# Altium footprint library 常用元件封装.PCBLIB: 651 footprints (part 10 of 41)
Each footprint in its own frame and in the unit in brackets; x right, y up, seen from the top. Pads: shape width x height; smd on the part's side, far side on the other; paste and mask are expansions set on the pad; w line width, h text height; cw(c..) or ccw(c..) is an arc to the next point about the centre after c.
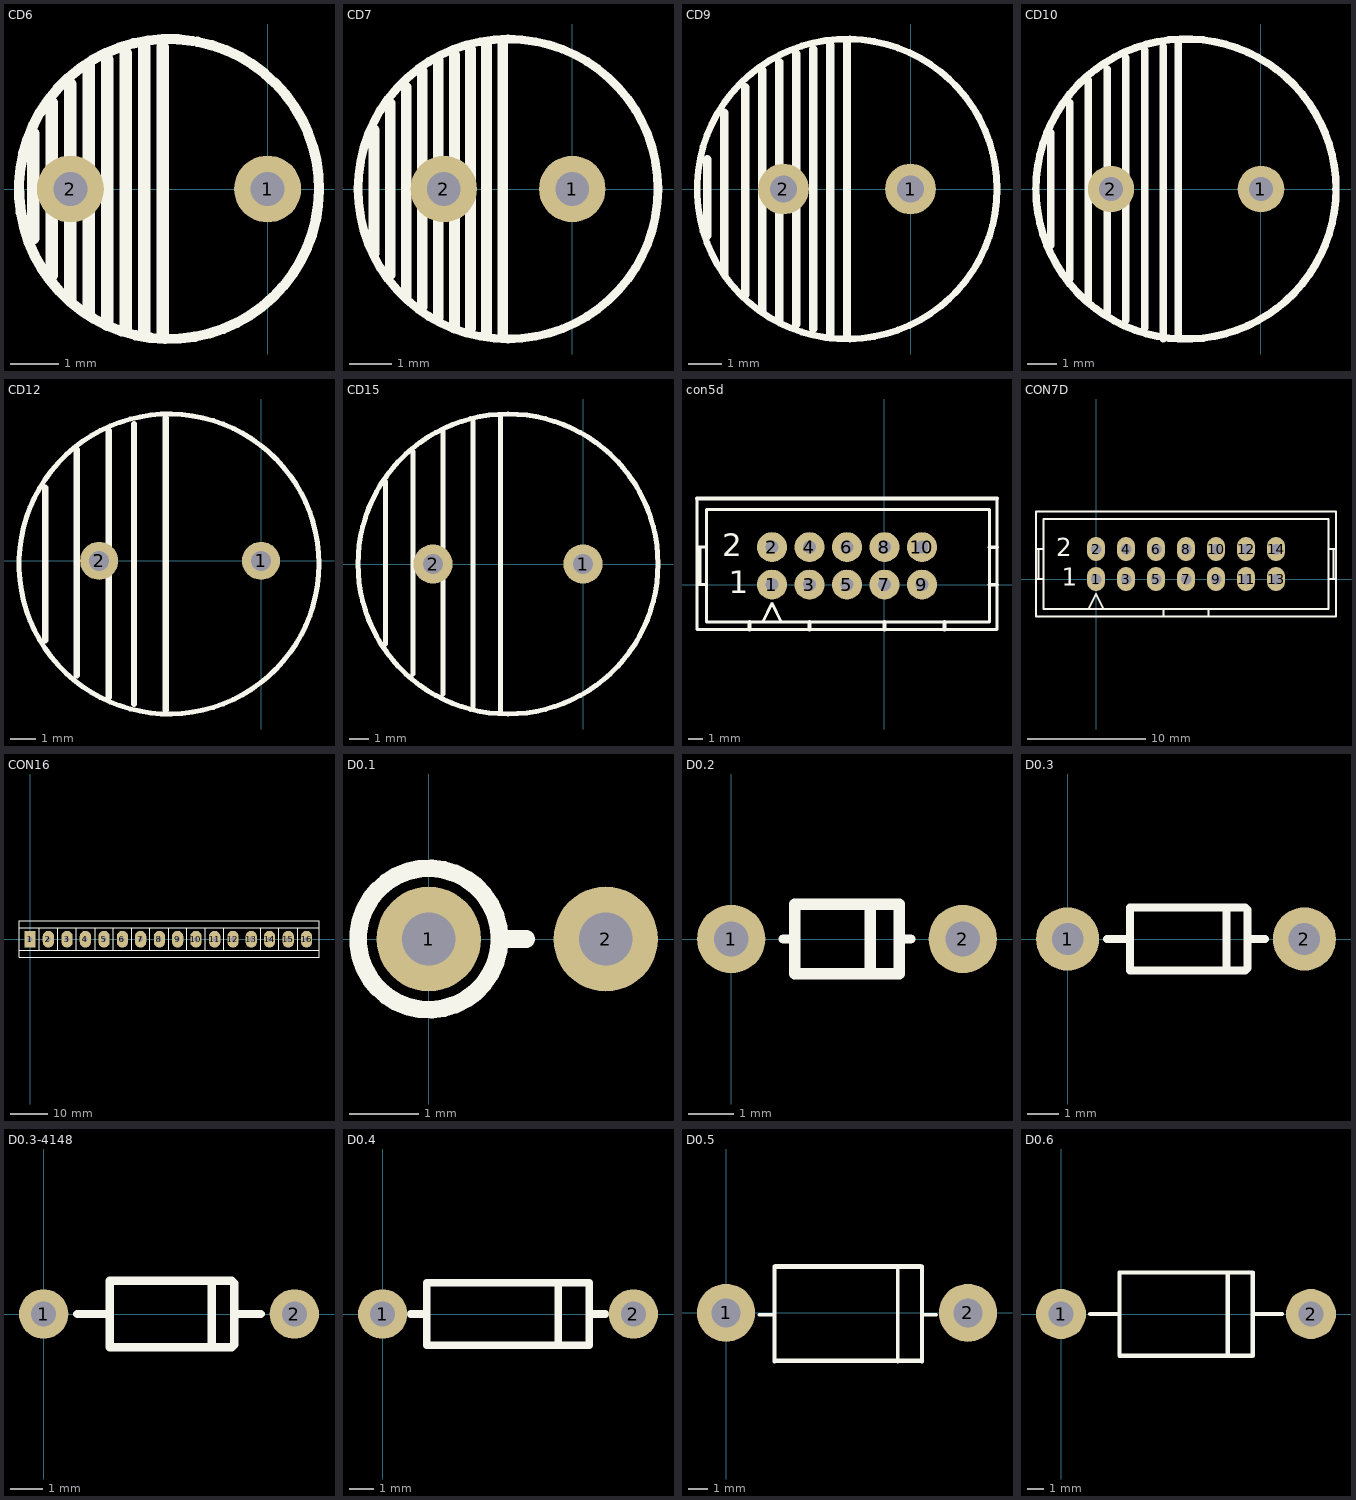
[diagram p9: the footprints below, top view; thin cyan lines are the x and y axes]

## CD6 [mm]
pads (2):
  round 1.38 hole 0.7: 1(0,0) 2(-4.064,0)
TopOverlay:
  lines w0.21: -1.549,3.052 ccw(c-2.032,0) -1.442,3.033
  lines w0.254: -4.826,-1.016 -4.826,1.143 ; -4.445,-1.778 -4.445,1.778 ; -4.064,-2.286 -4.064,2.159 ; -3.683,-2.54 -3.683,2.54 ; -3.302,-2.794 -3.302,2.667 ; -2.921,-2.921 -2.921,2.794 ; -2.54,-2.921 -2.54,2.921 ; -2.159,-3.048 -2.159,2.921

## CD7 [mil]
pads (2):
  round 62 hole 31.5: 1(0,0) 2(-120,0)
TopOverlay:
  circle w8: c-60,0 r140
  lines w10: -185,-60 -185,55 ; -170,-80 -170,80 ; -155,-100 -155,95 ; -140,-110 -140,110 ; -125,-120 -125,120 ; -110,-130 -110,125 ; -95,-130 -95,130 ; -80,-135 -80,135 ; -65,-135 -65,135

## CD9 [mil]
pads (2):
  round 60 hole 31.5: 1(0,0) 2(-150,0)
TopOverlay:
  circle w7.87: c-75,0 r177.16
  lines w10: -240,-55 -240,35 ; -220,-100 -220,90 ; -195,-125 -195,120 ; -175,-145 -175,140 ; -155,-155 -155,150 ; -135,-160 -135,160 ; -115,-165 -115,165 ; -95,-175 -95,170 ; -75,-175 -75,175

## CD10 [mil]
pads (2):
  round 62 hole 31.5: 1(0,0) 2(-200,0)
TopOverlay:
  circle w10: c-100,0 r200
  lines w10: -280,-75 -280,75 ; -255,-120 -255,115 ; -230,-150 -230,145 ; -205,-165 -205,160 ; -180,-175 -180,175 ; -155,-185 -155,185 ; -130,-200 -130,190 ; -110,-200 -110,195

## CD12 [mil]
pads (2):
  round 60 hole 31.5: 1(0,0) 2(-255,0)
TopOverlay:
  circle w7.87: c-145,-5 r236.22
  lines w10: -340,-125 -340,115 ; -290,-180 -290,175 ; -240,-215 -240,205 ; -200,-225 -200,215 ; -150,-235 -150,225

## CD15 [mm]
pads (2):
  round 2 hole 1: 1(0,0) 2(-7.62,0)
TopOverlay:
  circle w0.254: c-3.81,0 r7.62
  lines w0.254: -10.033,-4.064 -10.033,4.191 ; -8.636,-5.588 -8.636,5.715 ; -7.112,-6.604 -7.112,6.731 ; -5.588,-7.239 -5.588,7.239 ; -4.191,-7.493 -4.191,7.493

## con5d [mil]
pads (10):
  round 80 hole 35: 1(-300,0) 2(-300,100) 3(-200,0) 4(-200,100) 5(-100,0) 6(-100,100) 7(0,0) 8(0,100) 9(100,0) 10(100,100)
TopOverlay:
  lines w8: -500,0 -475,0 ; -500,100 -475,100 ; -500,230 -500,-120 300,-120 300,230 ; -491.67,0 -491.67,100 ; -325,-100 -300,-50 -275,-100 ; -475,-100 -75,-100 75,-100 280,-100 280,200 -475,200 -475,-100
  lines w10: -500,230 300,230 ; -360,-120 -360,-100 ; -200,-120 -200,-100 ; 0,-120 0,-100 ; 160,-120 160,-100 ; 280,0 300,0 ; 280,100 300,100
  text "2" at -432,76 h60
  text "1" at -415,-23 h60

## CON7D [mil]
pads (14):
  oval 60x80 hole 35: 1(0,0) 2(0,100) 3(100,0) 4(100,100) 5(200,0) 6(200,100) 7(300,0) 8(300,100) 9(400,0) 10(400,100) 11(500,0) 12(500,100) 13(600,0) 14(600,100)
TopOverlay:
  lines w8: -200,0 -175,0 ; -200,100 -175,100 ; -191.67,0 -191.67,100 ; -25,-100 0,-50 25,-100 ; 225,-125 225,-100 ; 375,-125 375,-100 ; 775,0 800,0 ; 775,100 800,100 ; 791.67,0 791.67,100 ; 225,-100 -175,-100 -175,200 775,200 775,-100 375,-100 ; 225,-100 375,-100 ; -200,-125 -200,225 800,225 800,-125 -200,-125
  text "1" at -115,-23 h60
  text "2" at -132,76 h60

## CON16 [mil]
pads (16):
  rect 120x180 hole 50: 1(0,0)
  oval 120x180 hole 50: 2(195,0) 3(395,0) 4(590,0) 5(790,0) 6(985,0) 7(1180,0) 8(1380,0) 9(1575,0) 10(1770,0) 11(1970,0) 12(2165,0) 13(2360,0) 14(2555,0) 15(2755,0) 16(2950,0)
TopOverlay:
  lines w12: -118,-116 3083,-116 ; -118,120 3083,120 ; 99,-117 99,118 ; 294,-112 294,118 ; 494,-112 494,118 ; 694,-112 694,118 ; 889,-112 889,118 ; 1084,-112 1084,118 ; 1279,-112 1279,118 ; 1479,-112 1479,118 ; 1674,-112 1674,118 ; 1869,-112 1869,118 ; 2069,-112 2069,118 ; 2459,-112 2459,118 ; 2654,-112 2654,118 ; 2854,-112 2854,118 ; -118,-195 3083,-195 3083,199 -118,199 -118,-195

## D0.1 [mm] "2.54mm"
pads (2):
  round 1.5 hole 0.762: 1(0,0) 2(2.54,0)
TopOverlay:
  circle w0.254: c0,0 r1.016
  lines w0.254: 1.143,0 1.397,0

## D0.2 [mm] "5.08mm IN4148 或贴片"
height 1
pads (2):
  round 1.5 hole 0.762: 1(0,0) 2(5.08,0)
TopOverlay:
  lines w0.2: 1.143,0 1.397,0 ; 3.683,0 3.937,0
  lines w0.254: 3.048,-0.762 3.048,0.762 ; 1.397,-0.762 1.397,0.762 3.683,0.762 3.683,-0.762 1.397,-0.762

## D0.3 [mil] "7.62mm IN4148 IN4007"
height 39.37
pads (2):
  round 80 hole 40: 1(0,0) 2(300,0)
TopOverlay:
  lines w10: 50,0 79,0 ; 79,-40 79,40 ; 80,-40 225,-40 228,-37 228,37 225,40 80,40 ; 201.33,-40 201.33,40 ; 228,0 250,0

## D0.3-4148 [mm] "7.62mm IN4148"
height 1
pads (2):
  round 1.5 hole 0.762: 1(0,0) 2(7.62,0)
TopOverlay:
  lines w0.254: 1.016,0 2.007,0 ; 2.007,-1.016 2.007,1.016 ; 2.032,-1.016 5.715,-1.016 5.791,-0.94 5.791,0.94 5.715,1.016 2.032,1.016 ; 5.114,-1.016 5.114,1.016 ; 5.791,0 6.604,0

## D0.4 [mm] "10.16mm IN4006 IN5399"
height 2
pads (2):
  round 2 hole 1.016: 1(0,0) 2(10.16,0)
TopOverlay:
  lines w0.305: 1.143,0 1.778,0 ; 7.112,-1.27 7.112,1.27 ; 8.382,0 9.017,0 ; 1.778,-1.27 8.382,-1.27 8.382,1.27 1.778,1.27 1.778,-1.27

## D0.5 [mil] "12.7mm IN5399 IN5408"
height 196.85
pads (2):
  round 120 hole 60: 1(0,0) 2(500,0)
TopOverlay:
  lines w7.87: 69,-4 100,-4 ; 100,-100.85 100,96 ; 355,-100.85 355,96 ; 405,-100.85 405,96 ; 405,-4 434,-4
  lines w10: 102,96 401.61,96 ; 104,-99 401.64,-99

## D0.6 [mil] "15.24mm IN5408 IN6A"
height 196.85
pads (2):
  round 120 hole 60: 1(0,0) 2(600,0)
TopOverlay:
  lines w10: 70,0 140,0 ; 400,-100 400,100 ; 460,0 530,0 ; 140,-100 460,-100 460,100 140,100 140,-100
